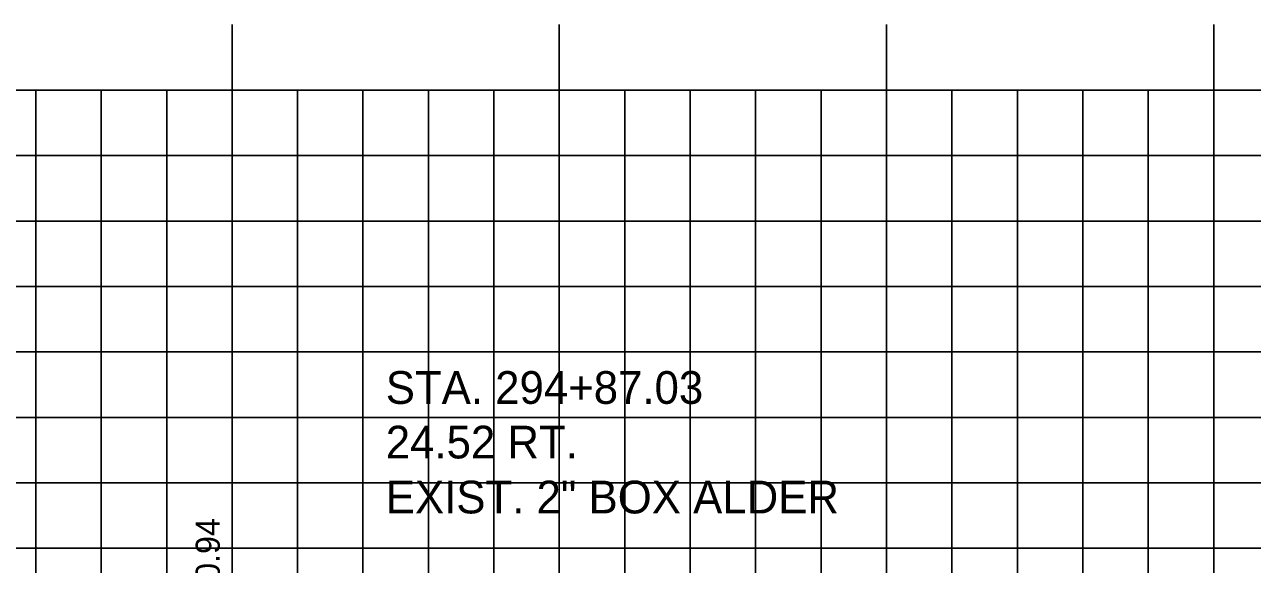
# Model space of a CAD drawing. Extents: x 859352 to 859522, y 366268 to 366378.
# Drawn here: x 859446.96 to 859465.72, y 366349.99 to 366358.24 of the extents above; entities that cross this region are included whole.
import ezdxf

# ---------------------------------------------------------------- set-up
doc = ezdxf.new("R2010")
doc.units = 0
for name, color, linetype in [('D_Text_Monospaced', 7, 'Continuous'), ('D_Text_Standard', 7, 'Continuous'), ('MAJOR', 7, 'Continuous'), ('MINOR', 7, 'Continuous')]:
    doc.layers.add(name, color=color, linetype=linetype)

msp = doc.modelspace()

# ---------------------------------------------------------------- linework, layer by layer
at = {"layer": 'MAJOR'}
for p, q in [((859450.129, 366358.238), (859450.129, 366357.236)), ((859455.129, 366358.238), (859455.129, 366357.236)), ((859460.129, 366358.238), (859460.129, 366357.236)), ((859465.129, 366358.238), (859465.129, 366357.236)), ((859365.129, 366357.236), (859505.129, 366357.236)), ((859365.129, 366357.236), (859505.129, 366357.236)), ((859450.129, 366337.236), (859450.129, 366357.236)), ((859455.129, 366337.236), (859455.129, 366357.236)), ((859460.129, 366337.236), (859460.129, 366357.236)), ((859465.129, 366337.236), (859465.129, 366357.236)), ((859365.129, 366352.236), (859505.129, 366352.236))]:
    msp.add_line(p, q, dxfattribs=at)
at = {"layer": 'MINOR'}
for p, q in [((859447.129, 366337.236), (859447.129, 366357.236)), ((859448.129, 366337.236), (859448.129, 366357.236)), ((859449.129, 366337.236), (859449.129, 366357.236)), ((859451.129, 366337.236), (859451.129, 366357.236)), ((859452.129, 366337.236), (859452.129, 366357.236)), ((859453.129, 366337.236), (859453.129, 366357.236)), ((859454.129, 366337.236), (859454.129, 366357.236)), ((859456.129, 366337.236), (859456.129, 366357.236)), ((859457.129, 366337.236), (859457.129, 366357.236)), ((859458.129, 366337.236), (859458.129, 366357.236)), ((859459.129, 366337.236), (859459.129, 366357.236)), ((859461.129, 366337.236), (859461.129, 366357.236)), ((859462.129, 366337.236), (859462.129, 366357.236)), ((859463.129, 366337.236), (859463.129, 366357.236)), ((859464.129, 366337.236), (859464.129, 366357.236)), ((859365.129, 366356.236), (859505.129, 366356.236)), ((859365.129, 366355.236), (859505.129, 366355.236)), ((859365.129, 366354.236), (859505.129, 366354.236)), ((859365.129, 366353.236), (859505.129, 366353.236)), ((859365.129, 366351.236), (859505.129, 366351.236)), ((859365.129, 366350.236), (859505.129, 366350.236))]:
    msp.add_line(p, q, dxfattribs=at)

# ---------------------------------------------------------------- texts
at = {"layer": 'D_Text_Monospaced'}
for s, height, p in [('STA. 294+87.03', 0.49998, (859452.477, 366352.443)), ('24.52 RT.', 0.5, (859452.477, 366351.609)), ('EXIST. 2" BOX ALDER', 0.49998, (859452.477, 366350.769))]:
    msp.add_text(s, height=height, dxfattribs=at).set_placement(p)
at = {"layer": 'D_Text_Standard'}
msp.add_text(' EL.=250.94', height=0.36848, rotation=90, dxfattribs=at).set_placement((859449.941, 366348.026))

doc.saveas('drawing.dxf')
